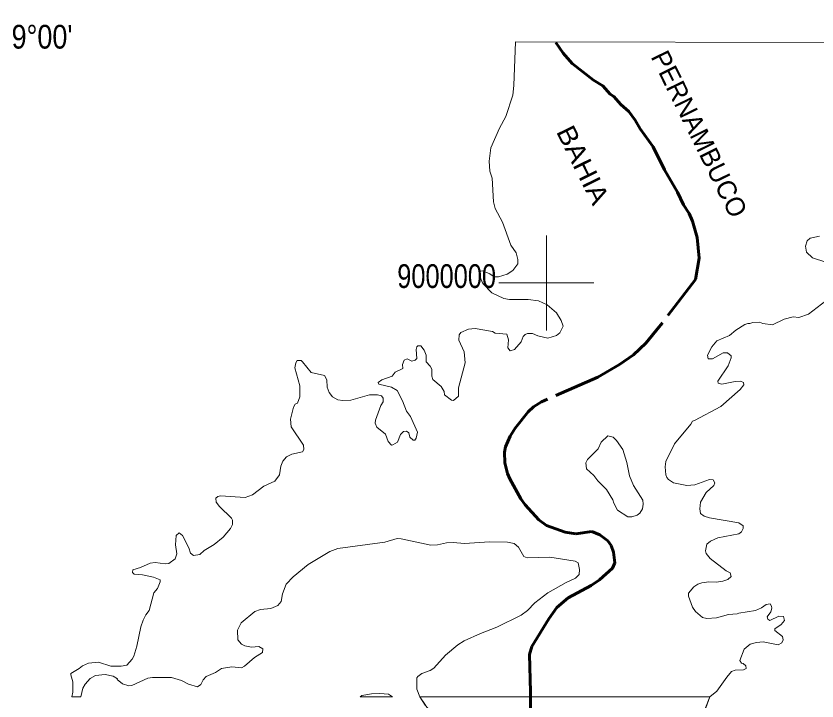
# Model space of a CAD drawing. Extents: x -1643653 to 4543381, y 1624270 to 13878484.
# Drawn here: x 563822 to 580704, y 8991189 to 9005626 of the extents above; entities that cross this region are included whole.
import ezdxf
from ezdxf.enums import TextEntityAlignment as Align

# ---------------------------------------------------------------- set-up
doc = ezdxf.new("R2010")
doc.units = 0
doc.header["$LTSCALE"] = 160
doc.linetypes.add('LONG_DASH_SHORT_DASH', pattern=[9.9, 6, -1.2, 1.5, -1.2])
doc.linetypes.add('MEDIUM_DASHED', pattern=[4.5, 3, -1.5])
for name, color, linetype, lineweight in [('2', 7, 'Continuous', 13), ('25', 7, 'Continuous', 13), ('46', 7, 'MEDIUM_DASHED', 70), ('60', 7, 'Continuous', 13), ('7', 7, 'LONG_DASH_SHORT_DASH', 60)]:
    doc.layers.add(name, color=color, linetype=linetype, lineweight=lineweight)
doc.layers.add('42', color=7, linetype='Continuous')
doc.layers.add('47', color=7, linetype='Continuous')

msp = doc.modelspace()

# ---------------------------------------------------------------- linework, layer by layer
at = {"layer": '2'}
for p, q in [((575000, 8999000), (575000, 9001000)), ((574000, 9000000), (576000, 9000000))]:
    msp.add_line(p, q, dxfattribs=at)
at = {"layer": '25'}
for p, q in [((587296.7, 9005052), (574348.1, 9005079.3)), ((571078.4, 8991274.5), (571756.4, 8991274.5)), ((572449.1, 8991100.5), (572334.3, 8991274.5)), ((578359.3, 8991047.5), (578446.9, 8991274.5))]:
    msp.add_line(p, q, dxfattribs=at)
for points in [[(574348.1, 9005079.3), (574317.4, 9004163), (574295.7, 9003956), (574144.4, 9003506.6), (574014.7, 9003264.2), (573829.1, 9002845.8), (573792.1, 9002568.4), (573811.5, 9002356.8), (573854.8, 9002205), (573887.2, 9001708), (573923.9, 9001569.9), (574075.2, 9001284.5), (574252.7, 9000793.7), (574360.6, 9000635.8), (574399.5, 9000497.4), (574399.6, 9000400.4), (574293.6, 9000261.8), (574170.4, 9000188.3), (573989.5, 9000125.8), (573897.6, 9000125.8), (573807.4, 9000194.6), (573651.6, 9000255.2), (573610.4, 9000246.4), (573582.4, 9000173.4), (573662.4, 8999991.6), (573850.3, 8999788.5), (574105.5, 8999671.6), (574225.9, 8999652.2), (574616, 8999647.8), (574834.5, 8999622.2), (575013.7, 8999535.3), (575214.5, 8999368.9), (575311.9, 8999208.8), (575350.7, 8999090.1), (575283.8, 8998949.8), (575211.7, 8998895.2), (575030.5, 8998839.4), (574820.5, 8998888.6), (574709.3, 8998932.6), (574600.8, 8998934.5), (574550.9, 8998912.8), (574512, 8998871.7), (574467, 8998760.2), (574328, 8998599.3), (574233.6, 8998567), (574187.8, 8998629.6), (574204.6, 8998800.2), (574169.9, 8998917.3), (573924.2, 8998943.1), (573861.2, 8998973.3), (573495.9, 8999038.2), (573357.6, 8999025.2), (573195.7, 8998954), (573160.9, 8998904.1), (573154.4, 8998796.3), (573264.6, 8998547.5), (573290.5, 8998318.6), (573147.9, 8997786.5), (573147.7, 8997610.4), (573041.5, 8997523.5), (573000.7, 8997531.6), (572856.3, 8997643.8), (572845.2, 8997713), (572780.5, 8997814.4), (572609.7, 8997966), (572588, 8998037.6), (572585.8, 8998184.3), (572553.4, 8998244.8), (572469.1, 8998340), (572464.8, 8998478.1), (572423.8, 8998581.8), (572354.7, 8998677), (572291.7, 8998674.9), (572271.2, 8998655.2), (572257.2, 8998599.6), (572268, 8998409.4), (572236.1, 8998375.1), (572164.3, 8998348.7), (572065.1, 8998398.3), (572002.4, 8998374.6), (571967.6, 8998284), (571974, 8998195.7), (571816.4, 8998119.6), (571747.1, 8998035.2), (571528.9, 8997959.6), (571454.6, 8997898.7), (571466.8, 8997864.9), (571737.3, 8997804.6), (571855.7, 8997734.5), (571967.5, 8997514.1), (572052.2, 8997299.3), (572136.7, 8997188.2), (572285.2, 8996857.2), (572259.3, 8996727.3), (572229.1, 8996686.3), (572195.3, 8996686.2), (572121.1, 8996746.8), (572103.5, 8996844.1), (572051.6, 8996874.3), (571987.6, 8996870.2), (571987.6, 8996870.2)], [(574348.1, 9005079.3), (574317.4, 9004163), (574295.7, 9003956), (574144.4, 9003506.6), (574014.7, 9003264.2), (573829.1, 9002845.8), (573792.1, 9002568.4), (573811.5, 9002356.8), (573854.8, 9002205), (573887.2, 9001708), (573923.9, 9001569.9), (574075.2, 9001284.5), (574252.7, 9000793.7), (574360.6, 9000635.8), (574399.5, 9000497.4), (574399.6, 9000400.4), (574293.6, 9000261.8), (574170.4, 9000188.3), (573989.5, 9000125.8), (573897.6, 9000125.8), (573807.4, 9000194.6), (573651.6, 9000255.2), (573610.4, 9000246.4), (573582.4, 9000173.4), (573662.4, 8999991.6), (573850.3, 8999788.5), (574105.5, 8999671.6), (574225.9, 8999652.2), (574616, 8999647.8), (574834.5, 8999622.2), (575013.7, 8999535.3), (575214.5, 8999368.9), (575311.9, 8999208.8), (575350.7, 8999090.1), (575283.8, 8998949.8), (575211.7, 8998895.2), (575030.5, 8998839.4), (574820.5, 8998888.6), (574709.3, 8998932.6), (574600.8, 8998934.5), (574550.9, 8998912.8), (574512, 8998871.7), (574467, 8998760.2), (574328, 8998599.3), (574233.6, 8998567), (574187.8, 8998629.6), (574204.6, 8998800.2), (574169.9, 8998917.3), (573924.2, 8998943.1), (573861.2, 8998973.3), (573495.9, 8999038.2), (573357.6, 8999025.2), (573195.7, 8998954), (573160.9, 8998904.1), (573154.4, 8998796.3), (573264.6, 8998547.5), (573290.5, 8998318.6), (573147.9, 8997786.5), (573147.7, 8997610.4), (573041.5, 8997523.5), (573000.7, 8997531.6), (572856.3, 8997643.8), (572845.2, 8997713), (572780.5, 8997814.4), (572609.7, 8997966), (572588, 8998037.6), (572585.8, 8998184.3), (572553.4, 8998244.8), (572469.1, 8998340), (572464.8, 8998478.1), (572423.8, 8998581.8), (572354.7, 8998677), (572291.7, 8998674.9), (572271.2, 8998655.2), (572257.2, 8998599.6), (572268, 8998409.4), (572236.1, 8998375.1), (572164.3, 8998348.7), (572065.1, 8998398.3), (572002.4, 8998374.6), (571967.6, 8998284), (571974, 8998195.7), (571816.4, 8998119.6), (571747.1, 8998035.2), (571528.9, 8997959.6), (571454.6, 8997898.7), (571466.8, 8997864.9), (571737.3, 8997804.6), (571855.7, 8997734.5), (571967.5, 8997514.1), (572052.2, 8997299.3), (572136.7, 8997188.2), (572285.2, 8996857.2), (572259.3, 8996727.3), (572229.1, 8996686.3), (572195.3, 8996686.2), (572121.1, 8996746.8), (572103.5, 8996844.1), (572051.6, 8996874.3), (571987.6, 8996870.2)], [(580893.5, 9000437), (580608.7, 9000531.7), (580484.7, 9000649.6), (580463.4, 9000778.4), (580500.2, 9000888.6), (580562.8, 9000942.6), (580759.6, 9000984)], [(580893.5, 9000437), (580608.7, 9000531.7), (580484.7, 9000649.6), (580463.4, 9000778.4), (580500.2, 9000888.6), (580562.8, 9000942.6), (580759.6, 9000984)], [(578829.1, 8998253.7), (578829.1, 8998253.7), (578893.5, 8998421.2), (578896, 8998462.9), (578820.3, 8998527.9), (578723.1, 8998528), (578498.5, 8998400.6), (578409.9, 8998402.6), (578394.5, 8998476.1), (578489.6, 8998655.6), (578593.2, 8998782.9), (578859, 8998891.1), (578995.7, 8999003.7), (579185.5, 8999124.5), (579245.2, 8999145.9), (579291.8, 8999144.2), (579351.3, 8999169.6), (579492.4, 8999170), (579561.6, 8999144.2), (579767.2, 8999116.1), (580013.9, 8999239.3), (580201.7, 8999282.4), (580318.7, 8999271.8), (580526.2, 8999343.3), (580889.2, 8999621.9)], [(578829.1, 8998253.7), (578829.1, 8998253.7), (578893.5, 8998421.2), (578896, 8998462.9), (578820.3, 8998527.9), (578723.1, 8998528), (578498.5, 8998400.6), (578409.9, 8998402.6), (578394.5, 8998476.1), (578489.6, 8998655.6), (578593.2, 8998782.9), (578859, 8998891.1), (578995.7, 8999003.7), (579185.5, 8999124.5), (579245.2, 8999145.9), (579291.8, 8999144.2), (579351.3, 8999169.6), (579492.4, 8999170), (579561.6, 8999144.2), (579767.2, 8999116.1), (580013.9, 8999239.3), (580201.7, 8999282.4), (580318.7, 8999271.8), (580526.2, 8999343.3), (580889.2, 8999621.9)], [(571987.6, 8996870.2), (571926.5, 8996807.2), (571865.9, 8996647.3), (571765.8, 8996584.6), (571736.3, 8996582.5), (571667.1, 8996658.1), (571606.5, 8996815.9), (571427, 8996963.1), (571394.8, 8997042.6), (571399.2, 8997108.2), (571513.5, 8997414.5), (571561.1, 8997492.8), (571561.1, 8997570.3), (571528.4, 8997620.1), (571442, 8997643.9), (571269.3, 8997639.5), (570879.9, 8997529.3), (570707.2, 8997522.8), (570605.6, 8997535.8), (570495.4, 8997602.8), (570421.8, 8997687.3), (570378.7, 8997803.8), (570376.4, 8997959.5), (570326.5, 8998050.2), (570039.3, 8998110.8), (569862.2, 8998339.7), (569828.8, 8998363.9), (569747.5, 8998367.9), (569719.3, 8998318.1), (569695.6, 8998210), (569803.5, 8997832.4), (569805.7, 8997600.4), (569753.7, 8997466.5), (569708.6, 8997447), (569671.8, 8997384.4), (569607, 8997125.3), (569624.2, 8996969.4), (569883.5, 8996580.5), (569890, 8996489.7), (569862.1, 8996442.2), (569634.2, 8996387.6), (569524.8, 8996331.6), (569444.9, 8996241), (569401.6, 8996135.2), (569377.7, 8995955.6), (569276.2, 8995821.7), (569042.7, 8995719.9), (568806.8, 8995531.7), (568653.5, 8995475.6), (568134.7, 8995512.3), (568072.2, 8995501.6), (568030.8, 8995462.5), (568041.7, 8995378.5), (568108.6, 8995287.8), (568364, 8995043), (568387.6, 8994997.6), (568385.5, 8994911.7), (568342.3, 8994825.1), (568190.7, 8994643.1), (567996.1, 8994487.5), (567788.8, 8994357.9), (567698, 8994275.9), (567560, 8994252.1), (567499.2, 8994304.1), (567462.2, 8994418.7), (567330.6, 8994677.7), (567263.6, 8994734), (567200.7, 8994675.1), (567183.6, 8994478), (567209.4, 8994288.5), (567174.9, 8994185.2), (567041.5, 8994087.6), (566962.8, 8994081.3), (566755.8, 8994109.3), (566652.7, 8994094.4), (566443.9, 8994001.2), (566287.2, 8993950.5), (566277.5, 8993895.3), (566309.1, 8993863.6), (566406.3, 8993853.8)], [(571987.6, 8996870.2), (571926.5, 8996807.2), (571865.9, 8996647.3), (571765.8, 8996584.6), (571736.3, 8996582.5), (571667.1, 8996658.1), (571606.5, 8996815.9), (571427, 8996963.1), (571394.8, 8997042.6), (571399.2, 8997108.2), (571513.5, 8997414.5), (571561.1, 8997492.8), (571561.1, 8997570.3), (571528.4, 8997620.1), (571442, 8997643.9), (571269.3, 8997639.5), (570879.9, 8997529.3), (570707.2, 8997522.8), (570605.6, 8997535.8), (570495.4, 8997602.8), (570421.8, 8997687.3), (570378.7, 8997803.8), (570376.4, 8997959.5), (570326.5, 8998050.2), (570039.3, 8998110.8), (569862.2, 8998339.7), (569828.8, 8998363.9), (569747.5, 8998367.9), (569719.3, 8998318.1), (569695.6, 8998210), (569803.5, 8997832.4), (569805.7, 8997600.4), (569753.7, 8997466.5), (569708.6, 8997447), (569671.8, 8997384.4), (569607, 8997125.3), (569624.2, 8996969.4), (569883.5, 8996580.5), (569890, 8996489.7), (569862.1, 8996442.2), (569634.2, 8996387.6), (569524.8, 8996331.6), (569444.9, 8996241), (569401.6, 8996135.2), (569377.7, 8995955.6), (569276.2, 8995821.7), (569042.7, 8995719.9), (568806.8, 8995531.7), (568653.5, 8995475.6), (568134.7, 8995512.3), (568072.2, 8995501.6), (568030.8, 8995462.5), (568041.7, 8995378.5), (568108.6, 8995287.8), (568364, 8995043), (568387.6, 8994997.6), (568385.5, 8994911.7), (568342.3, 8994825.1), (568190.7, 8994643.1), (567996.1, 8994487.5), (567788.8, 8994357.9), (567698, 8994275.9), (567560, 8994252.1), (567499.2, 8994304.1), (567462.2, 8994418.7), (567330.6, 8994677.7), (567263.6, 8994734), (567200.7, 8994675.1), (567183.6, 8994478), (567209.4, 8994288.5), (567174.9, 8994185.2), (567041.5, 8994087.6), (566962.8, 8994081.3), (566755.8, 8994109.3), (566652.7, 8994094.4), (566443.9, 8994001.2), (566287.2, 8993950.5), (566277.5, 8993895.3), (566309.1, 8993863.6), (566406.3, 8993853.8)], [(578446.9, 8991274.5), (578595.4, 8991394.1), (578801.1, 8991690.5), (578904.7, 8991809.2), (578982.8, 8991841.6), (579155.2, 8991848.1), (579213.7, 8991874.2), (579201.1, 8991927.8), (579146.8, 8991975.6), (579112.1, 8991984.6), (579075.6, 8992042.7), (579166.3, 8992278.3), (579295.8, 8992388.4), (579427.6, 8992423.1), (579570.5, 8992438.3), (579888.8, 8992373.7), (579965.9, 8992414.4), (579989.8, 8992474.5), (579975.3, 8992547.4), (579813.6, 8992672.6), (579818.5, 8992711.8), (579946.6, 8992799.3), (580015.8, 8992883.9), (579996.4, 8992972), (579903.2, 8992976.5), (579711.6, 8992886), (579670, 8992916.1), (579657.1, 8992961.4), (579728.3, 8993069.6), (579752, 8993147.2), (579747.7, 8993186.3), (579714.6, 8993238.2), (579635.4, 8993223), (579533.5, 8993151.6), (579406, 8993097.6), (579053.2, 8993043), (579021.4, 8993026.3), (578840, 8993009.1), (578582.4, 8992940.3), (578379.1, 8992925.9), (578292.9, 8992950.7), (578143.9, 8993075.8), (578083.2, 8993169), (577995.1, 8993400.6), (577994.6, 8993460.8), (578109.2, 8993594.8), (578195.8, 8993653.3), (578273.4, 8993681.3), (578427.8, 8993703), (578578, 8993693.5), (578718.8, 8993716), (578822.5, 8993752.7), (578893.8, 8993811.3), (578874.4, 8993888.2), (578790.1, 8993930), (578451.3, 8994193.1), (578370.9, 8994297.2), (578351.4, 8994355.6), (578379.6, 8994492.1), (578461.3, 8994556.7), (578615, 8994628.2), (579056.6, 8994710.7), (579110.2, 8994751.7), (579148.9, 8994826.5), (579144.5, 8994883.2), (579060.1, 8994943.9), (578441.8, 8995047.7), (578329.4, 8995084.5), (578249.8, 8995140.6), (578236.7, 8995240.2), (578245.4, 8995378.3), (578366.5, 8995580.6), (578530.6, 8995730.7), (578550, 8995787.2), (578517.8, 8995849.4), (578440.2, 8995858.2), (578130.8, 8995748), (577961.2, 8995733), (577680.9, 8995784.9), (577577.2, 8995854.1), (577540.6, 8995897.2), (577519, 8995958), (577506, 8996126), (577520.1, 8996237.3), (577700.6, 8996606.2), (578044.1, 8997021.1), (578079, 8997088.2), (578122.3, 8997097.1), (578675.5, 8997397.4), (579083.3, 8997753.4), (579161.9, 8997851.6), (579155.2, 8997899), (579090.3, 8997927), (578978.2, 8997924.9), (578697.2, 8997866.6), (578621.6, 8997888.2), (578612.9, 8997926.9), (578829.1, 8998253.7)], [(578446.9, 8991274.5), (578595.4, 8991394.1), (578801.1, 8991690.5), (578904.7, 8991809.2), (578982.8, 8991841.6), (579155.2, 8991848.1), (579213.7, 8991874.2), (579201.1, 8991927.8), (579146.8, 8991975.6), (579112.1, 8991984.6), (579075.6, 8992042.7), (579166.3, 8992278.3), (579295.8, 8992388.4), (579427.6, 8992423.1), (579570.5, 8992438.3), (579888.8, 8992373.7), (579965.9, 8992414.4), (579989.8, 8992474.5), (579975.3, 8992547.4), (579813.6, 8992672.6), (579818.5, 8992711.8), (579946.6, 8992799.3), (580015.8, 8992883.9), (579996.4, 8992972), (579903.2, 8992976.5), (579711.6, 8992886), (579670, 8992916.1), (579657.1, 8992961.4), (579728.3, 8993069.6), (579752, 8993147.2), (579747.7, 8993186.3), (579714.6, 8993238.2), (579635.4, 8993223), (579533.5, 8993151.6), (579406, 8993097.6), (579053.2, 8993043), (579021.4, 8993026.3), (578840, 8993009.1), (578582.4, 8992940.3), (578379.1, 8992925.9), (578292.9, 8992950.7), (578143.9, 8993075.8), (578083.2, 8993169), (577995.1, 8993400.6), (577994.6, 8993460.8), (578109.2, 8993594.8), (578195.8, 8993653.3), (578273.4, 8993681.3), (578427.8, 8993703), (578578, 8993693.5), (578718.8, 8993716), (578822.5, 8993752.7), (578893.8, 8993811.3), (578874.4, 8993888.2), (578790.1, 8993930), (578451.3, 8994193.1), (578370.9, 8994297.2), (578351.4, 8994355.6), (578379.6, 8994492.1), (578461.3, 8994556.7), (578615, 8994628.2), (579056.6, 8994710.7), (579110.2, 8994751.7), (579148.9, 8994826.5), (579144.5, 8994883.2), (579060.1, 8994943.9), (578441.8, 8995047.7), (578329.4, 8995084.5), (578249.8, 8995140.6), (578236.7, 8995240.2), (578245.4, 8995378.3), (578366.5, 8995580.6), (578530.6, 8995730.7), (578550, 8995787.2), (578517.8, 8995849.4), (578440.2, 8995858.2), (578130.8, 8995748), (577961.2, 8995733), (577680.9, 8995784.9), (577577.2, 8995854.1), (577540.6, 8995897.2), (577519, 8995958), (577506, 8996126), (577520.1, 8996237.3), (577700.6, 8996606.2), (578044.1, 8997021.1), (578079, 8997088.2), (578122.3, 8997097.1), (578675.5, 8997397.4), (579083.3, 8997753.4), (579161.9, 8997851.6), (579155.2, 8997899), (579090.3, 8997927), (578978.2, 8997924.9), (578697.2, 8997866.6), (578621.6, 8997888.2), (578612.9, 8997926.9), (578829.1, 8998253.7)], [(568487.1, 8992684.5), (568569.1, 8992838), (568854.8, 8993074), (568977.6, 8993117), (569194, 8993136.6), (569341.2, 8993199.5), (569413.7, 8993286.4), (569438.4, 8993446), (569516.9, 8993653.7), (569666.9, 8993803.6), (569976.6, 8994064), (570432.9, 8994338.6), (570607.5, 8994403.3), (571593.3, 8994539.5), (571853, 8994615.2), (571939.4, 8994608.7), (572566.4, 8994472.6), (572704.5, 8994483.3), (572894.9, 8994524.4), (573037.9, 8994528.7), (573275.2, 8994507.1), (573798.6, 8994543.9), (574179, 8994537.4), (574321.5, 8994509.3), (574410.9, 8994430.6), (574526.9, 8994235), (574593.8, 8994206.8), (575069.7, 8994217.5), (575607.7, 8994137.4), (575672.8, 8994102.6), (575700.9, 8993960), (575690, 8993856.5), (575611.7, 8993776), (575415.4, 8993683.4), (575030.8, 8993467.3), (574760.4, 8993259.6), (574604.9, 8993095.5)], [(568487.1, 8992684.5), (568569.1, 8992838), (568854.8, 8993074), (568977.6, 8993117), (569194, 8993136.6), (569341.2, 8993199.5), (569413.7, 8993286.4), (569438.4, 8993446), (569516.9, 8993653.7), (569666.9, 8993803.6), (569976.6, 8994064), (570432.9, 8994338.6), (570607.5, 8994403.3), (571593.3, 8994539.5), (571853, 8994615.2), (571939.4, 8994608.7), (572566.4, 8994472.6), (572704.5, 8994483.3), (572894.9, 8994524.4), (573037.9, 8994528.7), (573275.2, 8994507.1), (573798.6, 8994543.9), (574179, 8994537.4), (574321.5, 8994509.3), (574410.9, 8994430.6), (574526.9, 8994235), (574593.8, 8994206.8), (575069.7, 8994217.5), (575607.7, 8994137.4), (575672.8, 8994102.6), (575700.9, 8993960), (575690, 8993856.5), (575611.7, 8993776), (575415.4, 8993683.4), (575030.8, 8993467.3), (574760.4, 8993259.6), (574604.9, 8993095.5)], [(566406.3, 8993853.8), (566487.5, 8993845.6), (566720.4, 8993798.2), (566856.8, 8993741.9), (566861.3, 8993701.1), (566803.3, 8993560.8), (566725.3, 8993467.3), (566628, 8993095.8), (566556.6, 8993002.5), (566500.5, 8992892.5), (566452.8, 8992749.4), (566371.7, 8992344.8), (566307.9, 8992133.6), (566273.3, 8992070.6), (566159, 8991941.3), (566037.8, 8991923.8), (565822.3, 8991921.6), (565557.9, 8992003.8), (565347.2, 8991985.1), (565224.8, 8991932.3), (565151.5, 8991872), (564980.8, 8991770.3), (564976.4, 8991740.3), (564976.4, 8991740.3), (565017.4, 8991591.1), (565017.4, 8991374.7), (564994.9, 8991274.5), (565186.5, 8991274.5)], [(566406.3, 8993853.8), (566487.5, 8993845.6), (566720.4, 8993798.2), (566856.8, 8993741.9), (566861.3, 8993701.1), (566803.3, 8993560.8), (566725.3, 8993467.3), (566628, 8993095.8), (566556.6, 8993002.5), (566500.5, 8992892.5), (566452.8, 8992749.4), (566371.7, 8992344.8), (566307.9, 8992133.6), (566273.3, 8992070.6), (566159, 8991941.3), (566037.8, 8991923.8), (565822.3, 8991921.6), (565557.9, 8992003.8), (565347.2, 8991985.1), (565224.8, 8991932.3), (565151.5, 8991872), (564980.8, 8991770.3), (564976.4, 8991740.3), (564976.4, 8991740.3), (565017.4, 8991591.1), (565017.4, 8991374.7), (564994.9, 8991274.5), (565186.5, 8991274.5)], [(574604.9, 8993095.5), (574470.8, 8992998.2), (573958.5, 8992743.1), (573612.4, 8992613.3), (573265.1, 8992456.7), (573136.5, 8992373), (572873.3, 8992152.9), (572626.3, 8991880.2), (572549.3, 8991828.8), (572375.9, 8991770.2), (572289.7, 8991707.6), (572272.4, 8991674.5), (572272.4, 8991435), (572334.3, 8991274.5), (578446.9, 8991274.5)], [(574604.9, 8993095.5), (574470.8, 8992998.2), (573958.5, 8992743.1), (573612.4, 8992613.3), (573265.1, 8992456.7), (573136.5, 8992373), (572873.3, 8992152.9), (572626.3, 8991880.2), (572549.3, 8991828.8), (572375.9, 8991770.2), (572289.7, 8991707.6), (572272.4, 8991674.5), (572272.4, 8991435), (572334.3, 8991274.5)], [(565186.5, 8991274.5), (565229.4, 8991456.8), (565277, 8991543.6), (565385, 8991662.2), (565495.2, 8991724.9), (565699.6, 8991750.3), (565868.8, 8991714.1), (565962.8, 8991656.3), (565956, 8991638.4), (566069.6, 8991550.2), (566202.1, 8991510.9), (566262.2, 8991518.1), (566602.6, 8991670.9), (566699.3, 8991686), (567101.1, 8991683.8), (567313.2, 8991623.3), (567457.9, 8991543.5), (567647.8, 8991487.2), (567719.8, 8991534.9), (567767.4, 8991634.3), (567827.8, 8991705.4), (568027.3, 8991790.1), (568156.3, 8991874), (568371.7, 8991906.5), (568571.6, 8991889.4), (568638.4, 8991921.7), (568847.5, 8992104.9), (569018.9, 8992209.7), (569025.4, 8992289.9), (568938.9, 8992336.7), (568783.5, 8992319.5), (568643, 8992349.7), (568576.9, 8992385), (568495.8, 8992479.4), (568487.1, 8992684.5)], [(565186.5, 8991274.5), (565229.4, 8991456.8), (565277, 8991543.6), (565385, 8991662.2), (565495.2, 8991724.9), (565699.6, 8991750.3), (565868.8, 8991714.1), (565962.8, 8991656.3), (565956, 8991638.4), (566069.6, 8991550.2), (566202.1, 8991510.9), (566262.2, 8991518.1), (566602.6, 8991670.9), (566699.3, 8991686), (567101.1, 8991683.8), (567313.2, 8991623.3), (567457.9, 8991543.5), (567647.8, 8991487.2), (567719.8, 8991534.9), (567767.4, 8991634.3), (567827.8, 8991705.4), (568027.3, 8991790.1), (568156.3, 8991874), (568371.7, 8991906.5), (568571.6, 8991889.4), (568638.4, 8991921.7), (568847.5, 8992104.9), (569018.9, 8992209.7), (569025.4, 8992289.9), (568938.9, 8992336.7), (568783.5, 8992319.5), (568643, 8992349.7), (568576.9, 8992385), (568495.8, 8992479.4), (568487.1, 8992684.5)], [(571756.4, 8991274.5), (571671.1, 8991329.3), (571489.6, 8991346.6), (571316.8, 8991342.2), (571109.2, 8991305.4), (571078.4, 8991274.5)], [(571756.4, 8991274.5), (571671.1, 8991329.3), (571489.6, 8991346.6), (571316.8, 8991342.2), (571109.2, 8991305.4), (571078.4, 8991274.5)], [(578351.6, 8991043.2), (578446.9, 8991274.5), (572334.3, 8991274.5), (572447.3, 8991102.9), (572499.8, 8991033.9)]]:
    msp.add_lwpolyline(points, dxfattribs=at)
msp.add_lwpolyline([(576838, 8995728.5), (577030.4, 8995421.6), (577043.3, 8995335.1), (577023.9, 8995242.1), (576967.8, 8995145.1), (576915.8, 8995106), (576799.1, 8995073.5), (576714.8, 8995068.6), (576498.8, 8995207.4), (576421.1, 8995358), (576401.5, 8995430.7), (576267.3, 8995648.5), (576085.6, 8995830.3), (576000.3, 8995938.5), (575843.7, 8996083.1), (575828.5, 8996208.2), (575867.5, 8996280), (576094.2, 8996506.7), (576156.7, 8996642.5), (576293.1, 8996778.9), (576409.7, 8996749.2), (576479.1, 8996679.7), (576613.1, 8996489.7), (576693.2, 8996212.8), (576749.4, 8995936.1)], close=True, dxfattribs=at)
msp.add_lwpolyline([(576838, 8995728.5), (577030.4, 8995421.6), (577043.3, 8995335.1), (577023.9, 8995242.1), (576967.8, 8995145.1), (576915.8, 8995106), (576799.1, 8995073.5), (576714.8, 8995068.6), (576498.8, 8995207.4), (576421.1, 8995358), (576401.5, 8995430.7), (576267.3, 8995648.5), (576085.6, 8995830.3), (576000.3, 8995938.5), (575843.7, 8996083.1), (575828.5, 8996208.2), (575867.5, 8996280), (576094.2, 8996506.7), (576156.7, 8996642.5), (576293.1, 8996778.9), (576409.7, 8996749.2), (576479.1, 8996679.7), (576613.1, 8996489.7), (576693.2, 8996212.8), (576749.4, 8995936.1)], close=True, dxfattribs=at)
at = {"layer": '60', "lineweight": 25}
msp.add_spline([(814781, 9009175.5), (814787.2, 9009173.4), (814796.9, 9009173.4), (814799.4, 9009172.4), (814805.1, 9009174.5), (814805.6, 9009176.5), (814811.7, 9009179.5), (814811.7, 9009179.5), (814801.5, 9009181), (814790.7, 9009181.5), (814784.1, 9009183.1), (814777.4, 9009185.1), (814778.4, 9009175.5)], degree=3, dxfattribs=at)
at = {"layer": '7'}
msp.add_lwpolyline([(575200.8, 9005066), (575352.9, 9004840.4), (575540.7, 9004624.5), (575990.8, 9004276.1), (576191.4, 9004153), (576345, 9003982.4), (576418.6, 9003930.3), (576572.1, 9003761.7), (576736.2, 9003614.8), (576870.3, 9003433.3), (576976.4, 9003251.5), (577248.6, 9002866.9), (577488.7, 9002382.5), (577761.4, 9001910.5), (577888.7, 9001647.5), (578007.4, 9001466.1), (578081, 9001303.7), (578180.5, 9000960), (578223.7, 9000519.2), (578145.6, 9000073.3), (577379.3, 8999071.7), (577093.1, 8998733.4), (576838.2, 8998485), (576539.7, 8998279.4), (576081.4, 8998015.7), (574896.8, 8997496.8), (574728.1, 8997390.9), (574617.9, 8997285), (574345.3, 8996938.9), (574235.1, 8996770.3), (574135.8, 8996545.7), (574116.4, 8996433.3), (574127.2, 8996208.5), (574183.3, 8995983.9), (574230.8, 8995871.5), (574464.4, 8995447.5), (574555.2, 8995326.5), (574842.5, 8995008.9), (575001.4, 8994887.2), (575394, 8994749.3), (575618.8, 8994712.5), (575955.7, 8994764.3), (576124.6, 8994693), (576292.4, 8994562), (576364.1, 8994468.9), (576412.1, 8994327.7), (576440.1, 8994102.6), (576392.7, 8993990.5), (576122.7, 8993744.2), (575943, 8993623), (575458.6, 8993363.4), (575221, 8993160.3), (575052.4, 8992918.2), (574695.8, 8992339.1), (574641.7, 8992170), (574667.6, 8991383.4), (574663.3, 8991045.9)], dxfattribs=at)

# ---------------------------------------------------------------- texts
at = {"layer": '42'}
msp.add_text('PERNAMBUCO', height=400, rotation=296.367, dxfattribs=at).set_placement((578043.4, 9003051.2), align=Align.CENTER)
at = {"layer": '42', "width": 1.1}
msp.add_text('BAHIA', height=400, rotation=296.367, dxfattribs=at).set_placement((575591.3, 9002399), align=Align.CENTER)
at = {"layer": '46', "width": 0.85}
msp.add_text("9°00'", height=500, dxfattribs=at).set_placement((564370.9, 9004939.3), align=Align.CENTER)
at = {"layer": '47', "width": 0.8}
msp.add_text('9000000', height=500, dxfattribs=at).set_placement((572898.5, 8999894), align=Align.CENTER)

doc.saveas('drawing.dxf')
